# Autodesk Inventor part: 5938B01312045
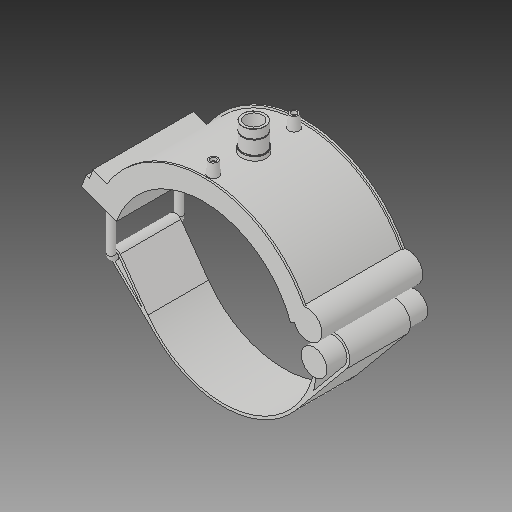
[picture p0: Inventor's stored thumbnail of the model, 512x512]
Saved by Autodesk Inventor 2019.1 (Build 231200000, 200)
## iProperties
Created: 2017-07
Part Number: 5938B01312045
Material: Generic
Description: PLASSON TRANSITION SADDLE 12''IPS x 1"NPT
Document SubType Name: Modeling
Designer: KIM
Density: 1 g/cm^3
Appearance: Default
Author: KIM
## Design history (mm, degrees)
derived "5938B.ipt"
feature "Solid1::5938B.ipt"
tag "TaggingFeature1"
body "Solid1"
other parameters: "d0" = 323.4, "d1" = 388.08, "d2" = 487.045, "d3" = 80.85, "d4" = 176.022, "d5" = 0, "d40" = 201.8016, "d41" = 42.4074, "d43" = 0, "d45" = 0, "d47" = 240.776, "d48" = 39.3783, "d50" = 0, "d78" = 216.04, "d79" = 15, "d80" = 70.4088, "d82" = 5 deg, "d84" = 4, "d85" = 14, "d86" = 0, "d87" = 3, "d88" = 0, "d96" = 395.8416, "d97" = 3.52044, "d98" = 0, "d102" = 0.90873, "d103" = 30.291, "d104" = 28.0416, "d105" = 0, "d106" = 24.2328, "d108" = 0, "d109" = -15.57867, "d111" = 0.5, "d112" = 0.5, "d113" = 0, "d114" = 0.5, "d117" = 0.30291, "d120" = 140 deg, "d121" = 24.228, "d122" = 20 deg, "d123" = 1552.32, "d124" = 232.848, "d126" = 0, "d143" = 333.102, "d145" = 49.75385, "d149" = 4.851, "d150" = 54.72923, "d153" = 176.022, "d154" = 0, "d156" = 194.04, "d157" = 160 deg, "d159" = 12.936, "d161" = 4.851, "d162" = 105.6132, "d163" = 0, "d164" = 161.7, "d167" = 32.34, "d168" = 189.30732, "d170" = 4.851, "d172" = 0, "d173" = 1, "d175" = 161.7, "d176" = 20 deg, "d177" = 22.638, "d178" = 64.68, "d180" = 0, "d183" = 25.872, "d184" = 18.1104, "d185" = 57.20715, "d186" = 57.20715, "d187" = 194.04, "d188" = 19.404, "d189" = 22.638, "d190" = 0, "d191" = 232.848, "d193" = 12.936, "d194" = 6.6297, "d195" = 90 deg, "d197" = 0, "d199" = 0, "d_" = 323.4, "B_" = 194.818, "H_" = 46.736, "L_" = 176.022, "d_t" = 6, "G_" = 30.291, "d148" = 4.851, "d160" = 4.851, "d169" = 4.851, "d192" = 12.936
